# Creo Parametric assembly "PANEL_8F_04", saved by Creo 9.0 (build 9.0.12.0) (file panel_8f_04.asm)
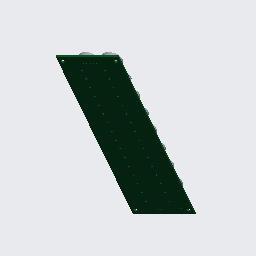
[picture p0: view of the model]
Units: millimeter Newton Second (mmNs); MM, TONNE, SECS

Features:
  1. coordinate system "PANEL_8F_04"
  2. imported feature "Import Feature id 4"
  3. component "PCB_8F"
  4. component "TX_8F_T1"
  5. component "TX_8F_T1"
  6. component "TX_8F_T1"
  7. component "TX_8F_T1"
  8. component "TX_8F_T1"
  9. component "TX_8F_T1"
  10. component "TX_8F_T1"
  11. component "TX_8F_T1"
  12. component "TX_8F_T1"
  13. component "TX_8F_T1"
  14. component "TX_8F_T1"
  15. component "TX_8F_T1"
  16. component "TX_8F_T1"
  17. component "TX_8F_T1"
  18. component "TX_8F_T1"
  19. component "TX_8F_T1"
